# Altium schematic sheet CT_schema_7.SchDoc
size 274 x 160 mm
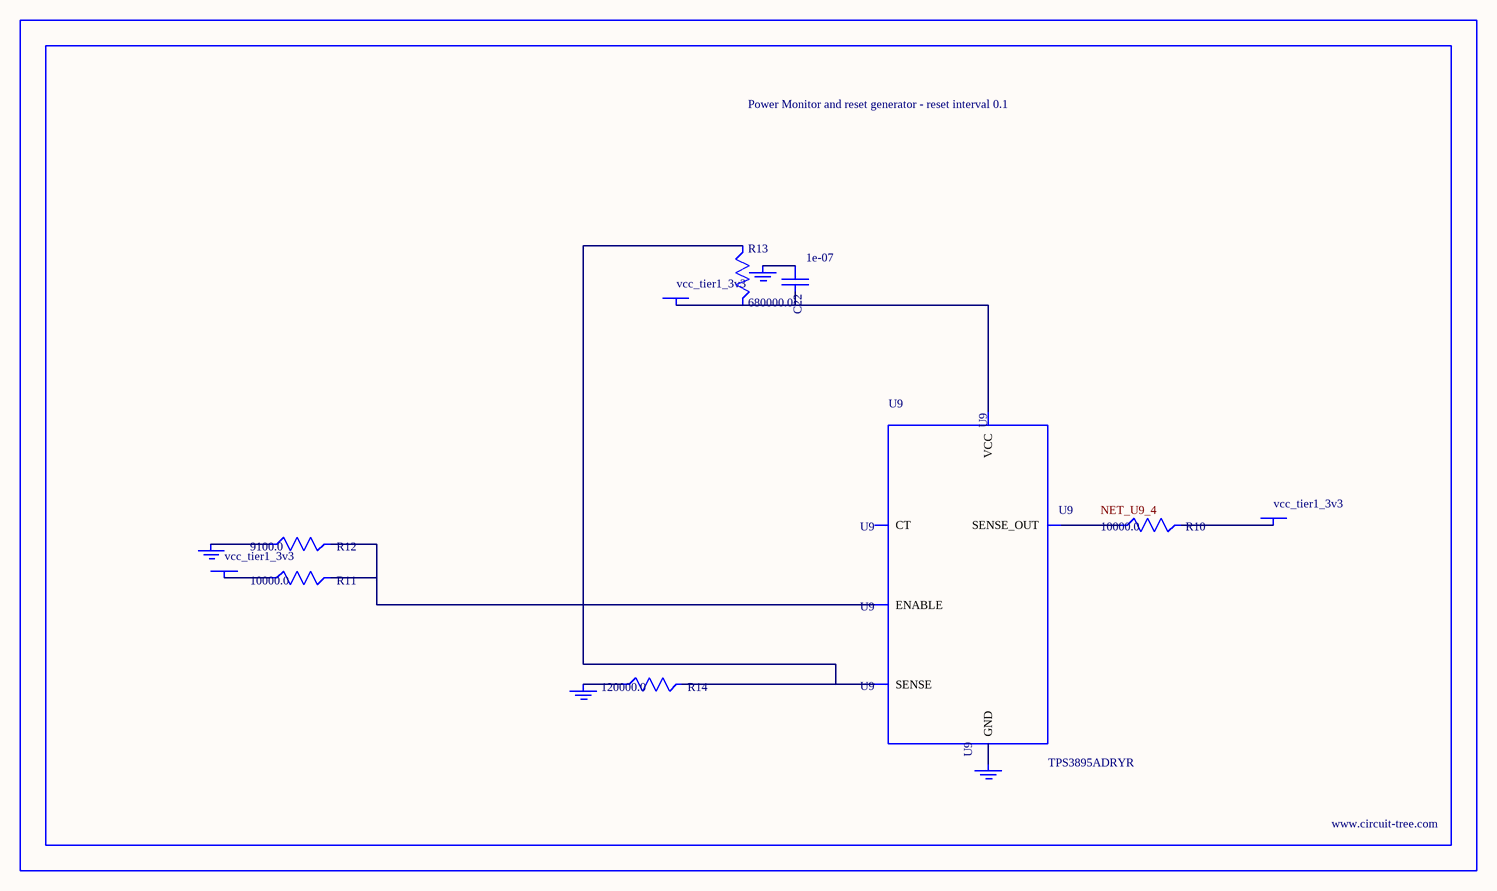
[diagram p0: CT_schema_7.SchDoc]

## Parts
BORDER6  (no value)
C22  1e-07  [C0402]
GND_INSTANCE_6_0  (no value)
GND_INSTANCE_6_1  (no value)
GND_INSTANCE_6_2  (no value)
GND_INSTANCE_6_3  (no value)
POWER_INSTANCE_6_0  vcc_tier1_3v3
POWER_INSTANCE_6_1  vcc_tier1_3v3
POWER_INSTANCE_6_2  vcc_tier1_3v3
R10  10000.0  [R0603]
R11  10000.0  [R0603]
R12  9100.0  [R0603]
R13  680000.0  [R0603]
R14  120000.0  [R0603]
U9  TPS3895ADRYR  [SON-6]

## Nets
NetC22_1: C22.1 GND_INSTANCE_6_2.0(GND)
NetC22_2: C22.2 POWER_INSTANCE_6_2.0(PWR) R13.2 U9.6(VCC)
NetGND_INSTANCE_6_0_0: GND_INSTANCE_6_0.0(GND) R12.1
NetGND_INSTANCE_6_1_0: GND_INSTANCE_6_1.0(GND) R14.1
NetGND_INSTANCE_6_3_0: GND_INSTANCE_6_3.0(GND) U9.2(GND)
NetPOWER_INSTANCE_6_0_0: POWER_INSTANCE_6_0.0(PWR) R11.1
NetPOWER_INSTANCE_6_1_0: POWER_INSTANCE_6_1.0(PWR) R10.2
NetR10_1: R10.1 U9.4(SENSE_OUT)
NetR11_2: R11.2 R12.2 U9.1(ENABLE)
NetR13_1: R13.1 R14.2 U9.3(SENSE)

Not connected (* = marked no-connect by the designer): U9 5(CT)

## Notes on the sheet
- Labels drawn without touching a wire or pin: NET_U9_4

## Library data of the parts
BORDER6 = BORDER_PAGE6
C22 = C0402C104K3RACTU
GND_INSTANCE_6_0-GND_INSTANCE_6_3 = GND
POWER_INSTANCE_6_0-POWER_INSTANCE_6_2 = PWR
R10 R11 = RC0603JR-0710KL
R12 = RC0603JR-079K1L
R13 = RC0603JR-07680KL
R14 = RC0603JR-07120KL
